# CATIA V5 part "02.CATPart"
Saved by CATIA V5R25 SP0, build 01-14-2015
Part number: 02
Bounding box of the stored display mesh (mm): x -4 to 4, y -37.5 to 37.5, z -3.804 to 3.804
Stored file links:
  D:\feridun18052022montaj\02.CATPart
  D:\feridun18052022montaj\cektirme.CATProduct
  D:\feridun18052022montaj\03.CATPart
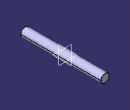
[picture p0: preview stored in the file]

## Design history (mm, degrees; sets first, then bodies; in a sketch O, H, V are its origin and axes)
Body1 (main body)
  Sketch1 on zx-plane, origin (0, 0, 0), H (-1, 0, 0), V (0, 0, 1)
    circle A1 centre (0, 0) radius 4
    radius A1 = 4
  Pad1: profile Sketch1, direction (0, 1, 0), length 37.5, mirrored extent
